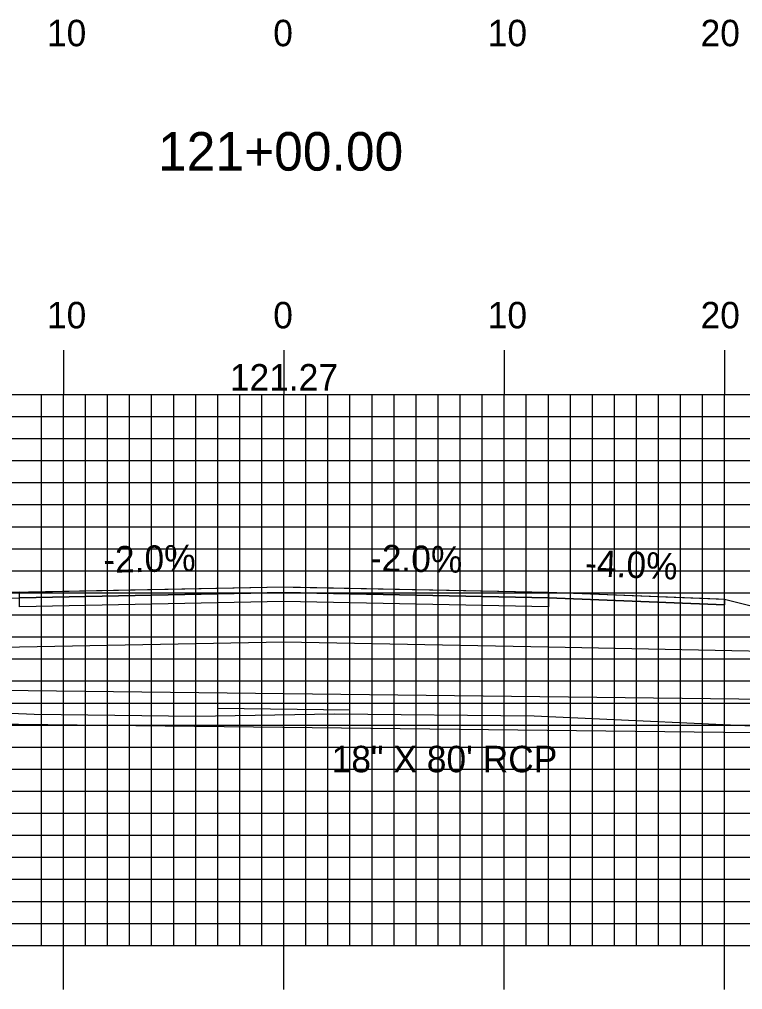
# Model space of a CAD drawing. Extents: x 1772022 to 1772366, y 442591 to 442811.
# Drawn here: x 1772176.09 to 1772208.91, y 442696.66 to 442740.68 of the extents above; entities that cross this region are included whole.
import ezdxf

# ---------------------------------------------------------------- set-up
doc = ezdxf.new("R2010")
doc.units = 0
for name, color, linetype in [('ANNOTATION', 7, 'Continuous'), ('D_Drainage_Culvert', 7, 'Continuous'), ('D_Drainage_Text', 7, 'Continuous'), ('D_Roadway_Centerline', 7, 'Continuous'), ('D_Roadway_Centerline_Text', 7, 'Continuous'), ('D_Roadway_Edge_Shoulder', 7, 'Continuous'), ('D_Roadway_Edge_TW', 7, 'Continuous'), ('D_Roadway_Pavement', 7, 'Continuous'), ('D_Roadway_SubGrade', 7, 'Continuous'), ('H_V ANNOTATION', 7, 'Continuous'), ('MAJOR', 7, 'Continuous'), ('MINOR', 7, 'Continuous'), ('S_Roadway_Centerline', 7, 'Continuous')]:
    doc.layers.add(name, color=color, linetype=linetype)

msp = doc.modelspace()

# ---------------------------------------------------------------- linework, layer by layer
at = {"layer": 'D_Drainage_Culvert'}
msp.add_line((1772185.094, 442709.424), (1772191.094, 442709.356), dxfattribs=at)
for points in [[(1772151.388, 442710.511), (1772149.389, 442710.534), (1772149.371, 442709.012), (1772229.366, 442708.104)], [(1772229.366, 442708.104), (1772229.383, 442709.604), (1772149.389, 442710.534)]]:
    msp.add_lwpolyline(points, dxfattribs=at)
at = {"layer": 'D_Roadway_Centerline'}
msp.add_lwpolyline([(1772156.094, 442711.374), (1772157.92, 442711.83), (1772158.274, 442711.919), (1772168.094, 442714.373), (1772175.815, 442714.682), (1772176.094, 442714.693), (1772176.512, 442714.702), (1772188.094, 442714.933), (1772188.512, 442714.925), (1772200.094, 442714.693), (1772207.815, 442714.385), (1772208.094, 442714.373), (1772217.913, 442711.918), (1772218.267, 442711.83), (1772218.796, 442711.698), (1772221.743, 442710.961)], dxfattribs=at)
at = {"layer": 'D_Roadway_Edge_Shoulder'}
for points in [[(1772176.094, 442714.693), (1772168.094, 442714.373), (1772168.094, 442714.123), (1772176.094, 442714.443)], [(1772200.094, 442714.693), (1772208.094, 442714.373), (1772208.094, 442714.123), (1772200.094, 442714.443)]]:
    msp.add_lwpolyline(points, close=True, dxfattribs=at)
at = {"layer": 'D_Roadway_Edge_TW'}
msp.add_lwpolyline([(1772176.094, 442714.443), (1772176.094, 442714.693), (1772188.094, 442714.933), (1772200.094, 442714.693), (1772200.094, 442714.443), (1772188.094, 442714.683)], close=True, dxfattribs=at)
at = {"layer": 'D_Roadway_Pavement'}
msp.add_lwpolyline([(1772176.094, 442714.027), (1772176.094, 442714.443), (1772188.094, 442714.683), (1772200.094, 442714.443), (1772200.094, 442714.027), (1772188.094, 442714.267)], close=True, dxfattribs=at)
at = {"layer": 'D_Roadway_SubGrade'}
msp.add_lwpolyline([(1772176.094, 442712.193), (1772157.92, 442711.83), (1772168.094, 442714.373), (1772168.094, 442714.123), (1772176.094, 442714.443), (1772188.094, 442714.683), (1772200.094, 442714.443), (1772208.094, 442714.123), (1772208.094, 442714.373), (1772218.267, 442711.83), (1772200.094, 442712.193), (1772188.094, 442712.433)], close=True, dxfattribs=at)
at = {"layer": 'MAJOR'}
for p, q in [((1772178.094, 442725.669), (1772178.094, 442723.665)), ((1772188.094, 442725.669), (1772188.094, 442723.665)), ((1772198.094, 442725.669), (1772198.094, 442723.665)), ((1772208.094, 442725.669), (1772208.094, 442723.665)), ((1772048.094, 442723.665), (1772328.094, 442723.665)), ((1772048.094, 442723.665), (1772328.094, 442723.665)), ((1772178.094, 442698.665), (1772178.094, 442723.665)), ((1772188.094, 442698.665), (1772188.094, 442723.665)), ((1772198.094, 442698.665), (1772198.094, 442723.665)), ((1772208.094, 442698.665), (1772208.094, 442723.665)), ((1772048.094, 442718.665), (1772328.094, 442718.665)), ((1772048.094, 442713.665), (1772328.094, 442713.665)), ((1772048.094, 442708.665), (1772328.094, 442708.665)), ((1772048.094, 442703.665), (1772328.094, 442703.665)), ((1772048.094, 442698.665), (1772328.094, 442698.665)), ((1772048.094, 442698.665), (1772328.094, 442698.665)), ((1772178.094, 442696.661), (1772178.094, 442698.665)), ((1772188.094, 442696.661), (1772188.094, 442698.665)), ((1772198.094, 442696.661), (1772198.094, 442698.665)), ((1772208.094, 442696.661), (1772208.094, 442698.665))]:
    msp.add_line(p, q, dxfattribs=at)
at = {"layer": 'MINOR'}
for p, q in [((1772177.094, 442698.665), (1772177.094, 442723.665)), ((1772179.094, 442698.665), (1772179.094, 442723.665)), ((1772180.094, 442698.665), (1772180.094, 442723.665)), ((1772181.094, 442698.665), (1772181.094, 442723.665)), ((1772182.094, 442698.665), (1772182.094, 442723.665)), ((1772183.094, 442698.665), (1772183.094, 442723.665)), ((1772184.094, 442698.665), (1772184.094, 442723.665)), ((1772185.094, 442698.665), (1772185.094, 442723.665)), ((1772186.094, 442698.665), (1772186.094, 442723.665)), ((1772187.094, 442698.665), (1772187.094, 442723.665)), ((1772189.094, 442698.665), (1772189.094, 442723.665)), ((1772190.094, 442698.665), (1772190.094, 442723.665)), ((1772191.094, 442698.665), (1772191.094, 442723.665)), ((1772192.094, 442698.665), (1772192.094, 442723.665)), ((1772193.094, 442698.665), (1772193.094, 442723.665)), ((1772194.094, 442698.665), (1772194.094, 442723.665)), ((1772195.094, 442698.665), (1772195.094, 442723.665)), ((1772196.094, 442698.665), (1772196.094, 442723.665)), ((1772197.094, 442698.665), (1772197.094, 442723.665)), ((1772199.094, 442698.665), (1772199.094, 442723.665)), ((1772200.094, 442698.665), (1772200.094, 442723.665)), ((1772201.094, 442698.665), (1772201.094, 442723.665)), ((1772202.094, 442698.665), (1772202.094, 442723.665)), ((1772203.094, 442698.665), (1772203.094, 442723.665)), ((1772204.094, 442698.665), (1772204.094, 442723.665)), ((1772205.094, 442698.665), (1772205.094, 442723.665)), ((1772206.094, 442698.665), (1772206.094, 442723.665)), ((1772207.094, 442698.665), (1772207.094, 442723.665)), ((1772048.094, 442722.665), (1772328.094, 442722.665)), ((1772048.094, 442721.665), (1772328.094, 442721.665)), ((1772048.094, 442720.665), (1772328.094, 442720.665)), ((1772048.094, 442719.665), (1772328.094, 442719.665)), ((1772048.094, 442717.665), (1772328.094, 442717.665)), ((1772048.094, 442716.665), (1772328.094, 442716.665)), ((1772048.094, 442715.665), (1772328.094, 442715.665)), ((1772048.094, 442714.665), (1772328.094, 442714.665)), ((1772048.094, 442712.665), (1772328.094, 442712.665)), ((1772048.094, 442711.665), (1772328.094, 442711.665)), ((1772048.094, 442710.665), (1772328.094, 442710.665)), ((1772048.094, 442709.665), (1772328.094, 442709.665)), ((1772048.094, 442707.665), (1772328.094, 442707.665)), ((1772048.094, 442706.665), (1772328.094, 442706.665)), ((1772048.094, 442705.665), (1772328.094, 442705.665)), ((1772048.094, 442704.665), (1772328.094, 442704.665)), ((1772048.094, 442702.665), (1772328.094, 442702.665)), ((1772048.094, 442701.665), (1772328.094, 442701.665)), ((1772048.094, 442700.665), (1772328.094, 442700.665)), ((1772048.094, 442699.665), (1772328.094, 442699.665))]:
    msp.add_line(p, q, dxfattribs=at)
at = {"layer": 'S_Roadway_Centerline'}
msp.add_lwpolyline([(1772128.852, 442711.962), (1772131.709, 442711.835), (1772148.852, 442710.265), (1772152.553, 442710.074), (1772156.608, 442709.92), (1772164.461, 442710.097), (1772170.743, 442709.418), (1772176.765, 442709.154), (1772184.09, 442709.072), (1772190.39, 442709.167), (1772199.456, 442709.084), (1772211.32, 442708.546), (1772211.609, 442708.541), (1772211.934, 442708.524), (1772231.881, 442708.062), (1772235.01, 442707.943), (1772238.683, 442707.821), (1772252.594, 442707.133)], dxfattribs=at)

# ---------------------------------------------------------------- texts
at = {"layer": 'ANNOTATION'}
for s, rotation, p in [('-2.0%', 1.1458, (1772179.909, 442715.57)), ('-2.0%', 358.8542, (1772191.989, 442715.656)), ('-4.0%', 357.7094, (1772201.746, 442715.429))]:
    msp.add_text(s, height=1.2, rotation=rotation, dxfattribs=at).set_placement(p)
at = {"layer": 'D_Drainage_Text'}
msp.add_text('18" X 80\' RCP', height=1.2, dxfattribs=at).set_placement((1772190.261, 442706.522))
at = {"layer": 'D_Roadway_Centerline_Text'}
msp.add_text('121.27', height=1.2, dxfattribs=at).set_placement((1772185.643, 442723.844))
at = {"layer": 'H_V ANNOTATION'}
for s, height, p in [('10', 1.2, (1772177.344, 442739.465)), ('0', 1.2, (1772187.612, 442739.465)), ('10', 1.2, (1772197.344, 442739.465)), ('20', 1.2, (1772207.002, 442739.465)), ('121+00.00', 1.75, (1772182.382, 442733.821)), ('10', 1.2, (1772177.344, 442726.665)), ('0', 1.2, (1772187.612, 442726.665)), ('10', 1.2, (1772197.344, 442726.665)), ('20', 1.2, (1772207.002, 442726.665))]:
    msp.add_text(s, height=height, dxfattribs=at).set_placement(p)

doc.saveas('drawing.dxf')
